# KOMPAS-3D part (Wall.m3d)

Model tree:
1. Plane XY
2. Plane ZX
3. Plane ZY
4. X Axis
5. Y Axis
6. Z Axis
7. Origin
8. Sketch:1
9. Extrude:1
     Wall Thickness 1 = 1; Wall Thickness 2 = 1; Distance 1 = 3000; Distance 2 = 10
10. Sketch:2
11. Cut-Extrude:1
     Wall Thickness 1 = 1; Wall Thickness 2 = 1; Distance 2 = 10; Distance 1 = 200

Referenced files in D:\Documents and Settings\kashirsky\Рабочий стол\Seminar\: Cottage.a3d
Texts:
  Steel DIN 17102
  Three Point Plane
  Plane at Angle
  Line and Point Plane
  Axis through Two Vertices
  Axis of Feature
  Axis of Conical Surface
  Axis through Edge
  Trim by Surface
  Trim by Sketch
  Feature with No History
  Intersection Axis of Two Planes
  Two Line Plane
  Line and Face Plane
  Bend by line
  Hole in sheet body
  Cut in sheet body
  Point in CM
  Linear Dimension from Line to Point
  Surface Finish Symbol
  Geometric Tolerance Symbol
  Leader #1
  Leader #2
  Leader #3
  Shape Deviations and Datum
  Node point number
  Mark of coordination axis
  Node point designation
  Mark/Reference designation with leader
  Mark/reference designation on line
  Mark/Reference designation without leader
